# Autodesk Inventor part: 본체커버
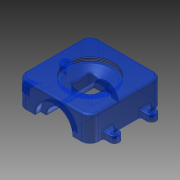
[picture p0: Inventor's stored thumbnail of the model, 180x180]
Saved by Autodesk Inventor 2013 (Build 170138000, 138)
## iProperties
Created: 2018-01
Part Number: 본체커버
Material: 알루미늄 6061
Document SubType Name: Modeling
Designer: mduedu
Density: 1 g/cm^3
Author: mduedu
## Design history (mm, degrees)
sketch "스케치1"
  geometry: L1 (55, 55)-(-55, 55); L2 (-55, 55)-(-55, -55); L3 (-55, -55)-(55, -55); L4 (55, -55)-(55, 55); L5 (55, 55)-(-55, -55); L6 (-55, 55)-(55, -55); 1 further point
  constraints: 12 end point, 2 midpoint, 2 parallel, 1 horizontal, 1 perpendicular
  dimensions: "d0" = 110 distance of L3.end L2.end; "d1" = 110 distance of L2.end L1.end
extrude "돌출1" new body sketch "스케치1" distance "d2" = 38; taper "d3" = 0 deg
revolve "회전1" stored, may be unused: angle "d13" = 90 deg
fillet "모깎기1" dims "d14" = 1
fillet "모깎기2" dims "d15" = 13
fillet "모깎기3" dims "d16" = 3
sketch "스케치3"
  geometry: L1 (-15, -15)-(15, -15); L2 (15, -15)-(15, 15); L3 (15, 15)-(-15, 15); L4 (-15, 15)-(-15, -15); L5 (42, 55)-(-42, 55) reference; L6 (-15, -15)-(15, 15); L7 (15, -15)-(-15, 15); 2 further points
  constraints: 12 end point, 2 parallel, 1 horizontal, 1 midpoint, 1 perpendicular, 1 vertical alignment
  dimensions: "d19" = 30 distance of L3.end L1.start; "d20" = 30 distance between parallel lines of L2 L4; "d65" = 40 distance between parallel lines of L5 L3
extrude "돌출2" cut sketch "스케치3" stored distance "d21" = 38; taper "d22" = 0 deg
fillet "모깎기4" dims "d23" = 3
sketch "스케치4"
  geometry: L1 (38, 35)-(32, 35); L2 (32, 35)-(32, 31); L3 (32, 31)-(25, 15); L4 (25, 15)-(25, 0); L5 (25, 0)-(38, 0); L6 (38, 0)-(38, 35); L7 (38, 42)-(38, -42) reference; 1 further point
  constraints: 12 end point, 2 parallel, 1 collinear, 1 horizontal, 1 horizontal alignment, 1 perpendicular
  dimensions: "d24" = 6 distance of L1.start L1.end; "d26" = 70 diameter of L1 L5; "d28" = 62 diameter of L2.end L5; "d29" = 30 diameter of L3.end L5; "d30" = 7 horizontal distance of L2.end L3.end
revolve "회전2" sketch "스케치4" stored, may be unused: angle "d31" = 90 deg
feature "스레드1" dims "d74" = 10, "d75" = 0
chamfer "모따기2" distance "d36" = 1; stored, may be unused: second distance "d37" = 2, angle "d38" = 45 deg
sketch "스케치5"
  geometry: L1 (-42, 55)-(-29, 55) reference; L2 (-55, -42)-(-55, 42) reference; L3 (42, -55)-(-42, -55) reference; L4 (55, 42)-(55, -42) reference; L5 (55, 35)-(65, 35); L6 (65, 21)-(55, 21); L7 (55, 21)-(55, 35); L8 (55, 42)-(55, -42) reference; L9 (28, 54)-(28, 47) reference; L10 (28, 47)-(20, 47) reference; L11 (19, 46)-(19, -24) reference; L12 (18, -25)-(7.5, -25) reference; L13 (7.5, -25)-(5.479, -28.5) reference; L14 (4.613, -29)-(-4.613, -29) reference; L15 (-5.479, -28.5)-(-7.5, -25) reference; L16 (-7.5, -25)-(-18, -25) reference; L17 (-19, -24)-(-19, 46) reference; L18 (-20, 47)-(-28, 47) reference; L19 (-28, 47)-(-28, 54) reference; L20 (19, 46)-(20, 47) reference; L21 (-20, 47)-(-19, 46) reference; L22 (-29, 55)-(-28, 54) reference; L23 (29, 55)-(42, 55) reference; L24 (28, 54)-(29, 55) reference; A1 r 13 centre (-42, 42) between (-42, 55) and (-55, 42) reference; A2 r 13 centre (-42, -42) between (-55, -42) and (-42, -55) reference; A3 r 13 centre (42, -42) between (42, -55) and (55, -42) reference; A4 r 13 centre (42, 42) between (55, 42) and (42, 55) reference; A5 r 7 centre (65, 28) between (65, 21) and (65, 35); A6 r 1 centre (18, -24) between (18, -25) and (19, -24) reference; A7 r 1 centre (4.613, -28) between (4.613, -29) and (5.479, -28.5) reference; A8 r 1 centre (-4.613, -28) between (-5.479, -28.5) and (-4.613, -29) reference; A9 r 1 centre (-18, -24) between (-19, -24) and (-18, -25) reference; 1 further point
  constraints: 6 end point, 2 point on circle, 2 tangent, 1 centre point, 1 collinear, 1 horizontal, 1 parallel, 1 point on line
  dimensions: "d39" = 14 distance between parallel lines of L6 L5; "d41" = 28 vertical distance of A5.centre point (0, 0); "d42" = 10 distance from line of A5.centre L4
extrude "돌출3" join sketch "스케치5" distance "d43" = 10; taper "d44" = 0 deg
fillet "모깎기6" dims "d45" = 1
fillet "모깎기7" dims "d46" = 3
sketch "스케치6"
  geometry: A1 r 7 centre (-65, 28) between (-65, 35) and (-65, 21) reference; A2 r 7 centre (-65, -28) between (-65, -21) and (-65, -35) reference; A3 r 7 centre (65, -28) between (65, -35) and (65, -21) reference; A4 r 7 centre (65, 28) between (65, 21) and (65, 35) reference; 5 further points
  constraints: 4 coincident
sketch "스케치7"
  geometry: 4 further points
  constraints: 4 other
hole "구멍1" sketch "스케치7" at (-65, 28), (65, 28), (-65, -28), (65, -28) diameter "d47" = 4.5; stored, may be unused: countersink angle "d51" = 90 deg, drill point angle "d53" = 0 deg; dims "d48" = 6, "d49" = 8, "d50" = 4.6, "d52" = 8
sketch "스케치9" dims "d66" = 46
  geometry: 3 further points
  constraints: 2 vertical alignment, 1 coincident, 2 other
hole "구멍2" sketch "스케치9" at (0, 23) diameter "d67" = 3.242; stored, may be unused: countersink angle "d71" = 90 deg, drill point angle "d73" = 118 deg; dims "d68" = 9, "d69" = 4, "d70" = 2, "d72" = 11
sketch "스케치8"
  geometry: L1 (-97, 35)-(-97, 0) reference; L2 (0, 38)-(-84, 38) reference; 2 further points
  constraints: 1 other
  dimensions: "d54" = 55 distance from line of point (-42, 23) L1; "d55" = 15 distance from line of point (-42, 23) L2
feature "엠보싱1" sketch "스케치8" dims "d0" = 110, "d1" = 110, "d56" = 0.5, "d57" = 0
node "솔리드1"
mirror "대칭1"
mirror "대칭2"
sketch "스케치2"
  geometry: L1 (-55, 55)-(55, 55) reference; L2 (-55, -55)-(-55, 55) reference; L3 (55, -55)-(-55, -55) reference; L4 (55, 55)-(55, -55) reference; L5 (0, 55)-(28, 55); L6 (19, 47)-(19, -25); L7 (19, -25)-(7.5, -25); L8 (0, -25.854)-(0, 55); L9 (7.5, -25)-(5.191, -29); L10 (5.191, -29)-(0, -29); L11 (0, -29)-(0, -25.854); L12 (19, 47)-(28, 47); L13 (28, 47)-(28, 55); 1 further point
  constraints: 18 end point, 2 horizontal, 2 perpendicular, 1 midpoint, 1 parallel, 1 point on line, 1 vertical
  dimensions: "d7" = 38 diameter of L6 L8; "d58" = 4 distance between parallel lines of L7 L10; "d59" = 30 deg angle of L8 L9; "d60" = 15 diameter of L7.end L8; "d61" = 56 diameter of L13 L8; "d62" = 8 distance of L12.end L5.end; "d63" = 84 distance between parallel lines of L10 L5
node "투영된 루프1"
node "투영된 루프2"
